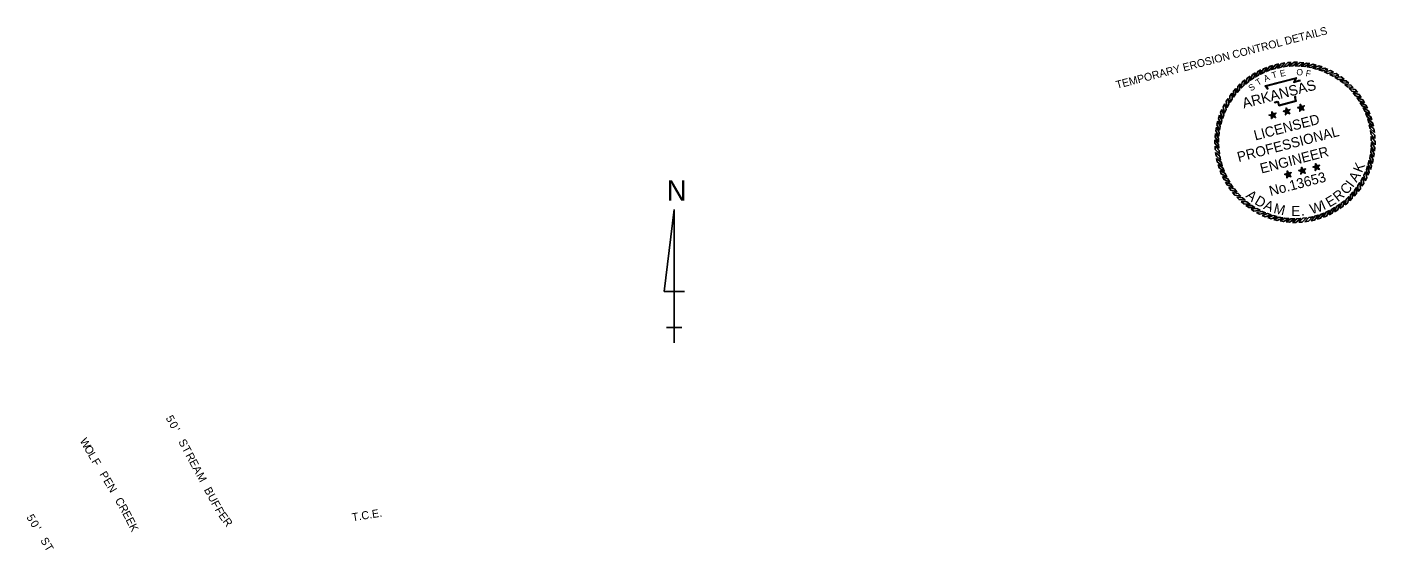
# Model space of a CAD drawing. Extents: x 833706 to 836451, y 495860 to 497794.
# Drawn here: x 835245 to 836255, y 496986 to 497378 of the extents above; entities that cross this region are included whole.
import ezdxf

# ---------------------------------------------------------------- set-up
doc = ezdxf.new("R2010")
doc.units = 0
for name, color, linetype in [('1', 7, 'Continuous'), ('8', 7, 'Continuous'), ('G-ANNO-STMP-AEW', 7, 'Continuous'), ('G-ANNO-TEXT', 7, 'Continuous'), ('Level 1', 7, 'Continuous'), ('R_Draft', 7, 'Continuous')]:
    doc.layers.add(name, color=color, linetype=linetype)

msp = doc.modelspace()

# ---------------------------------------------------------------- linework, layer by layer
at = {"layer": 'G-ANNO-STMP-AEW'}
for points in [[(836173.7, 497347.8), (836171.3, 497346.9), (836169.1, 497342.8), (836171.6, 497344)], [(836178.2, 497349.3), (836175.7, 497348.6), (836173.2, 497344.7), (836175.8, 497345.7)], [(836182.7, 497350.5), (836180.2, 497349.9), (836177.4, 497346.2), (836180.1, 497347)], [(836187.4, 497351.2), (836184.8, 497350.9), (836181.8, 497347.4), (836184.5, 497348)], [(836192.1, 497351.6), (836189.5, 497351.5), (836186.2, 497348.3), (836188.9, 497348.7)], [(836196.8, 497351.7), (836194.2, 497351.7), (836190.6, 497348.8), (836193.4, 497349)], [(836201.5, 497351.4), (836198.9, 497351.6), (836195.1, 497349), (836197.9, 497348.9)], [(836206.1, 497350.7), (836203.6, 497351.1), (836199.6, 497348.8), (836202.4, 497348.5)], [(836210.7, 497349.6), (836208.2, 497350.2), (836204.1, 497348.2), (836206.8, 497347.7)], [(836215.2, 497348.2), (836212.8, 497349), (836208.5, 497347.3), (836211.2, 497346.6)], [(836219.6, 497346.4), (836217.2, 497347.4), (836212.8, 497346.1), (836215.4, 497345.2)], [(836157.4, 497338.5), (836155.4, 497336.9), (836154.6, 497332.4), (836156.6, 497334.3)], [(836161.2, 497341.3), (836159.1, 497339.8), (836157.9, 497335.4), (836160.1, 497337.1)], [(836165.2, 497343.8), (836163, 497342.5), (836161.4, 497338.2), (836163.7, 497339.7)], [(836169.4, 497346), (836167, 497344.9), (836165.2, 497340.7), (836167.6, 497342)], [(836223.8, 497344.3), (836221.5, 497345.5), (836217, 497344.5), (836219.6, 497343.4)], [(836227.8, 497341.9), (836225.7, 497343.2), (836221.1, 497342.6), (836223.5, 497341.3)], [(836231.7, 497339.1), (836229.6, 497340.7), (836225, 497340.4), (836227.3, 497338.9)], [(836235.3, 497336.1), (836233.3, 497337.8), (836228.7, 497337.9), (836231, 497336.2)], [(836147.5, 497328.5), (836146, 497326.4), (836146.2, 497321.8), (836147.7, 497324.2)], [(836150.5, 497332.1), (836148.8, 497330.1), (836148.7, 497325.6), (836150.4, 497327.8)], [(836153.8, 497335.5), (836152, 497333.6), (836151.5, 497329.1), (836153.4, 497331.1)], [(836238.6, 497332.8), (836236.8, 497334.6), (836232.3, 497335.1), (836234.3, 497333.2)], [(836241.7, 497329.2), (836240.1, 497331.2), (836235.6, 497332), (836237.5, 497330)], [(836244.5, 497325.4), (836243, 497327.5), (836238.6, 497328.7), (836240.3, 497326.6)], [(836140.2, 497316.4), (836139.2, 497314), (836140.5, 497309.6), (836141.5, 497312.2)], [(836142.3, 497320.6), (836141.1, 497318.3), (836142.1, 497313.8), (836143.2, 497316.4)], [(836144.8, 497324.7), (836143.4, 497322.5), (836144, 497317.9), (836145.3, 497320.4)], [(836188.9, 497314.8), (836189.3, 497315.8), (836188.2, 497317.5), (836188.1, 497315.5)], [(836188.9, 497314.8), (836189.9, 497314.8), (836191.2, 497316.3), (836189.3, 497315.8)], [(836199.5, 497317.6), (836198.7, 497318.3), (836196.8, 497317.8), (836198.6, 497317)], [(836199.5, 497317.6), (836198.6, 497317), (836198.5, 497315), (836199.8, 497316.6)], [(836199.5, 497317.6), (836199.9, 497318.6), (836198.8, 497320.3), (836198.7, 497318.3)], [(836199.5, 497317.6), (836200.6, 497317.5), (836201.8, 497319.1), (836199.9, 497318.6)], [(836199.5, 497317.6), (836199.8, 497316.6), (836201.6, 497315.9), (836200.6, 497317.5)], [(836247, 497321.4), (836245.7, 497323.7), (836241.4, 497325.2), (836242.9, 497322.9)], [(836249.2, 497317.3), (836248, 497319.6), (836243.8, 497321.4), (836245.2, 497319)], [(836251, 497312.9), (836250.1, 497315.3), (836246, 497317.5), (836247.2, 497315)], [(836137, 497307.5), (836136.4, 497305), (836138.4, 497300.9), (836138.9, 497303.6)], [(836138.4, 497312), (836137.6, 497309.6), (836139.3, 497305.3), (836140, 497308)], [(836178.3, 497312.1), (836177.5, 497312.7), (836175.5, 497312.2), (836177.4, 497311.5)], [(836178.3, 497312.1), (836177.4, 497311.5), (836177.3, 497309.5), (836178.5, 497311.1)], [(836178.3, 497312.1), (836178.7, 497313.1), (836177.6, 497314.7), (836177.5, 497312.7)], [(836178.3, 497312.1), (836179.3, 497312), (836180.6, 497313.6), (836178.7, 497313.1)], [(836178.3, 497312.1), (836178.5, 497311.1), (836180.4, 497310.3), (836179.3, 497312)], [(836188.9, 497314.8), (836188.1, 497315.5), (836186.2, 497315), (836188, 497314.3)], [(836188.9, 497314.8), (836188, 497314.3), (836187.9, 497312.3), (836189.2, 497313.8)], [(836188.9, 497314.8), (836189.2, 497313.8), (836191, 497313.1), (836189.9, 497314.8)], [(836252.5, 497308.5), (836251.8, 497310.9), (836247.9, 497313.4), (836248.9, 497310.8)], [(836253.7, 497303.9), (836253.1, 497306.4), (836249.4, 497309.2), (836250.2, 497306.5)], [(836135.3, 497298.3), (836135, 497295.7), (836137.6, 497291.9), (836137.7, 497294.7)], [(836136, 497303), (836135.5, 497300.4), (836137.8, 497296.4), (836138.1, 497299.2)], [(836254.4, 497299.2), (836254.1, 497301.8), (836250.6, 497304.9), (836251.2, 497302.1)], [(836254.8, 497294.5), (836254.7, 497297.1), (836251.5, 497300.4), (836251.9, 497297.7)], [(836254.9, 497289.8), (836254.9, 497292.4), (836252, 497296), (836252.1, 497293.2)], [(836134.9, 497293.6), (836134.9, 497291), (836137.8, 497287.4), (836137.7, 497290.2)], [(836135, 497288.9), (836135.1, 497286.3), (836138.3, 497283), (836138, 497285.7)], [(836253.8, 497280.5), (836254.3, 497283), (836252, 497287), (836251.7, 497284.2)], [(836254.5, 497285.1), (836254.8, 497287.7), (836252.2, 497291.5), (836252.1, 497288.7)], [(836135.4, 497284.2), (836135.8, 497281.6), (836139.2, 497278.6), (836138.6, 497281.3)], [(836136.1, 497279.5), (836136.7, 497277), (836140.4, 497274.2), (836139.6, 497276.9)], [(836211.1, 497273.1), (836211.5, 497274.1), (836210.4, 497275.8), (836210.3, 497273.8)], [(836251.4, 497271.4), (836252.2, 497273.8), (836250.5, 497278.1), (836249.8, 497275.4)], [(836252.8, 497275.9), (836253.4, 497278.4), (836251.4, 497282.5), (836250.9, 497279.8)], [(836137.3, 497275), (836138.1, 497272.5), (836141.9, 497270), (836140.9, 497272.6)], [(836138.8, 497270.5), (836139.7, 497268.1), (836143.8, 497265.9), (836142.6, 497268.4)], [(836140.6, 497266.2), (836141.8, 497263.9), (836146, 497262), (836144.6, 497264.4)], [(836189.8, 497267.6), (836189, 497268.3), (836187.1, 497267.8), (836188.9, 497267)], [(836189.8, 497267.6), (836188.9, 497267), (836188.8, 497265.1), (836190.1, 497266.6)], [(836189.8, 497267.6), (836190.2, 497268.6), (836189.1, 497270.3), (836189, 497268.3)], [(836189.8, 497267.6), (836190.9, 497267.5), (836192.1, 497269.1), (836190.2, 497268.6)], [(836189.8, 497267.6), (836190.1, 497266.6), (836191.9, 497265.9), (836190.9, 497267.5)], [(836200.4, 497270.4), (836199.6, 497271), (836197.7, 497270.5), (836199.6, 497269.8)], [(836200.4, 497270.4), (836199.6, 497269.8), (836199.4, 497267.8), (836200.7, 497269.4)], [(836200.4, 497270.4), (836200.8, 497271.3), (836199.8, 497273), (836199.6, 497271)], [(836200.4, 497270.4), (836201.5, 497270.3), (836202.8, 497271.8), (836200.8, 497271.3)], [(836200.4, 497270.4), (836200.7, 497269.4), (836202.6, 497268.6), (836201.5, 497270.3)], [(836211.1, 497273.1), (836210.3, 497273.8), (836208.3, 497273.3), (836210.2, 497272.6)], [(836211.1, 497273.1), (836210.2, 497272.6), (836210.1, 497270.6), (836211.3, 497272.1)], [(836211.1, 497273.1), (836212.1, 497273.1), (836213.4, 497274.6), (836211.5, 497274.1)], [(836211.1, 497273.1), (836211.3, 497272.1), (836213.2, 497271.4), (836212.1, 497273.1)], [(836247.5, 497262.8), (836248.7, 497265.1), (836247.7, 497269.6), (836246.6, 497267)], [(836249.6, 497267), (836250.6, 497269.4), (836249.3, 497273.8), (836248.4, 497271.2)], [(836142.8, 497262), (836144.1, 497259.8), (836148.4, 497258.2), (836146.9, 497260.5)], [(836145.3, 497258), (836146.8, 497255.9), (836151.2, 497254.7), (836149.5, 497256.9)], [(836239.3, 497251.3), (836241, 497253.3), (836241.1, 497257.9), (836239.4, 497255.7)], [(836242.3, 497254.9), (836243.9, 497257), (836243.6, 497261.6), (836242.1, 497259.3)], [(836245.1, 497258.8), (836246.4, 497261), (836245.8, 497265.5), (836244.5, 497263.1)], [(836148.1, 497254.2), (836149.7, 497252.2), (836154.3, 497251.4), (836152.3, 497253.4)], [(836151.2, 497250.6), (836153, 497248.8), (836157.5, 497248.3), (836155.5, 497250.2)], [(836154.5, 497247.3), (836156.5, 497245.6), (836161.1, 497245.5), (836158.9, 497247.2)], [(836228.6, 497242.1), (836230.7, 497243.6), (836231.9, 497248), (836229.8, 497246.3)], [(836232.4, 497244.9), (836234.4, 497246.5), (836235.2, 497251.1), (836233.2, 497249.1)], [(836236, 497248), (836237.8, 497249.8), (836238.3, 497254.4), (836236.4, 497252.3)], [(836158.1, 497244.3), (836160.2, 497242.8), (836164.8, 497243), (836162.5, 497244.5)], [(836162, 497241.6), (836164.1, 497240.2), (836168.7, 497240.8), (836166.3, 497242.1)], [(836166, 497239.1), (836168.3, 497237.9), (836172.8, 497238.9), (836170.2, 497240)], [(836170.2, 497237), (836172.6, 497236), (836177, 497237.3), (836174.4, 497238.3)], [(836174.6, 497235.3), (836177, 497234.4), (836181.3, 497236.1), (836178.6, 497236.8)], [(836179.1, 497233.8), (836181.6, 497233.2), (836185.7, 497235.2), (836183, 497235.7)], [(836202.4, 497232.2), (836205, 497232.6), (836208.1, 497236), (836205.3, 497235.4)], [(836207.1, 497233), (836209.6, 497233.5), (836212.4, 497237.2), (836209.7, 497236.4)], [(836211.6, 497234.1), (836214.1, 497234.9), (836216.6, 497238.7), (836214, 497237.7)], [(836216.1, 497235.6), (836218.5, 497236.5), (836220.7, 497240.6), (836218.2, 497239.4)], [(836220.5, 497237.4), (836222.8, 497238.6), (836224.6, 497242.8), (836222.2, 497241.4)], [(836224.6, 497239.6), (836226.8, 497240.9), (836228.4, 497245.3), (836226.1, 497243.7)], [(836183.7, 497232.8), (836186.2, 497232.3), (836190.2, 497234.6), (836187.4, 497234.9)], [(836188.3, 497232.1), (836190.9, 497231.8), (836194.7, 497234.5), (836191.9, 497234.5)], [(836193, 497231.7), (836195.6, 497231.7), (836199.2, 497234.6), (836196.4, 497234.5)], [(836197.7, 497231.8), (836200.3, 497232), (836203.6, 497235.1), (836200.9, 497234.8)]]:
    msp.add_lwpolyline(points, close=True, dxfattribs=at)
for points in [[(836174.6, 497331.4), (836172.5, 497334), (836196, 497340.1), (836194.6, 497337.2), (836196.2, 497337.6), (836197.5, 497338), (836198.9, 497338.2)], [(836174.9, 497331.7), (836173.2, 497333.8), (836195.3, 497339.6), (836194, 497336.6), (836196.3, 497337.2), (836197.6, 497337.6), (836199, 497337.8)], [(836195.6, 497326.4), (836195.3, 497326), (836195.3, 497325.5), (836195.4, 497324.2), (836195.9, 497322.6), (836182.8, 497319.2), (836182.2, 497321.4), (836182.1, 497321.9), (836181.5, 497321.9), (836179.7, 497321.4), (836179.2, 497321.8)], [(836195.3, 497326.6), (836194.9, 497326.1), (836194.9, 497325.4), (836195.1, 497324.1), (836195.4, 497322.9), (836183.1, 497319.7), (836182.6, 497321.5), (836182.4, 497322.2), (836181.5, 497322.3), (836179.8, 497321.8), (836179.5, 497322.1)]]:
    msp.add_lwpolyline(points, dxfattribs=at)
at = {"layer": 'Level 1'}
for p, q in [((835729.7, 497241.5), (835722, 497179.9)), ((835729.7, 497141.5), (835729.7, 497241.5)), ((835729.7, 497241.5), (835729.7, 497164.5)), ((835722, 497179.9), (835737.4, 497179.9)), ((835729.7, 497141.5), (835729.7, 497164.5)), ((835729.7, 497153), (835723.9, 497153)), ((835723.9, 497153), (835735.4, 497153)), ((835729.7, 497141.5), (835729.7, 497153))]:
    msp.add_line(p, q, dxfattribs=at)

# ---------------------------------------------------------------- texts
at = {"layer": '1'}
msp.add_text('TEMPORARY EROSION CONTROL DETAILS', height=5.862, rotation=14.5644, dxfattribs=at).set_placement((836061.5, 497331.8))
at = {"layer": '8'}
for s, rotation, p in [('5', 298.0637, (835348.3, 497085.2)), ('0', 298.0637, (835350.9, 497080.5)), ("'", 298.0637, (835353.6, 497075.3)), ('S', 298.0637, (835357.8, 497067.4)), ('T', 298.0637, (835360.5, 497062.4)), ('R', 298.0637, (835363.2, 497057.2)), ('E', 298.0637, (835365.9, 497052.2)), ('A', 298.0637, (835368.4, 497047.5)), ('M', 298.0637, (835371.2, 497042.3)), ('B', 298.0637, (835377, 497031.4)), ('U', 298.0637, (835379.7, 497026.4)), ('F', 298.0637, (835382.4, 497021.3)), ('5', 301.0659, (835243.9, 497010.8)), ('F', 298.0637, (835385, 497016.5)), ('E', 306.2875, (835387.7, 497011.9)), ('T.C.E.', 9.2892, (835488.6, 497007.7)), ('0', 301.0659, (835246.6, 497006.2)), ("'", 301.0659, (835249.7, 497001.1)), ('R', 306.2875, (835390.9, 497007.6)), ('S', 301.0659, (835254.3, 496993.5)), ('T', 301.0659, (835257.2, 496988.6))]:
    msp.add_text(s, height=6, rotation=rotation, dxfattribs=at).set_placement(p)
at = {"layer": 'G-ANNO-TEXT'}
for s, height, rotation, p in [('O', 4.77, 355.7862, (836195.8, 497342.1)), ('ARKANSAS', 7.79, 14.5644, (836156.5, 497317.1)), ('T', 4.77, 31.4658, (836167.2, 497334)), ('A', 4.77, 23.2431, (836172.5, 497336.9)), ('T', 4.77, 16.0432, (836178.2, 497339.4)), ('E', 4.77, 11.2364, (836184.1, 497340.8)), ('F', 4.77, 349.9272, (836202.6, 497341.3)), ('S', 4.77, 34.3369, (836162, 497329.8)), ('LICENSED', 7.54, 14.5644, (836165.2, 497293.1)), ('PROFESSIONAL', 7.543, 14.5644, (836152.7, 497276.9)), ('ENGINEER', 7.54, 14.5644, (836169.8, 497268.3)), ('K', 7.54, 68.4114, (836245.1, 497268.5)), ('No.13653', 7.51, 14.5644, (836176.6, 497251.5)), ('A', 7.54, 59.7493, (836241.1, 497261.3)), ('R', 7.54, 38.726, (836227.1, 497246.8)), ('C', 7.54, 46.704, (836233.4, 497252)), ('I', 7.54, 52.9701, (836238.2, 497257.4)), ('A', 7.54, 320.5464, (836157.5, 497251)), ('D', 7.54, 328.8665, (836164, 497245.9)), ('A', 7.54, 337.1867, (836170.8, 497242)), ('M', 7.54, 346.3612, (836178.4, 497238.9)), ('W', 7.54, 16.6771, (836207.3, 497237.8)), ('I', 7.54, 24.1397, (836216.3, 497240.8)), ('E', 7.54, 30.5769, (836220.7, 497242.8)), ('E', 7.54, 359.8426, (836192.1, 497236.5)), ('.', 7.54, 5.4227, (836199.6, 497236.7))]:
    msp.add_text(s, height=height, rotation=rotation, dxfattribs=at).set_placement(p)
at = {"layer": 'Level 1'}
msp.add_text('N', height=15.4, rotation=360, dxfattribs=at).set_placement((835724, 497247.9))
at = {"layer": 'R_Draft'}
for s, rotation, p in [('W', 299.5944, (835283.9, 497068.1)), ('O', 299.8641, (835287.1, 497062.5)), ('L', 300.2411, (835290, 497057.4)), ('F', 300.6913, (835292.7, 497052.7)), ('P', 301.2077, (835298.6, 497043)), ('E', 301.1388, (835301.5, 497038.1)), ('N', 300.8693, (835304.3, 497033.5)), ('C', 299.5902, (835310.2, 497023.5)), ('R', 298.6275, (835313.1, 497018.5)), ('E', 297.7536, (835315.8, 497013.6)), ('E', 297.1516, (835318.3, 497008.8)), ('K', 296.7686, (835320.7, 497004))]:
    msp.add_text(s, height=6, rotation=rotation, dxfattribs=at).set_placement(p)

doc.saveas('drawing.dxf')
